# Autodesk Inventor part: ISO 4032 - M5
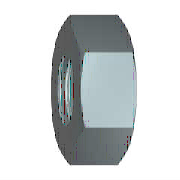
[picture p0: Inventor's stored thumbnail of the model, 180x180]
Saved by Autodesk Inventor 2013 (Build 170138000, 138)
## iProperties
Created: 2012-02
Part Number: ISO 4032 - M5
Material: Edelstahl, 440C
Description: Sechskantmuttern, Typ 1 - Produktklasse A und B
Document SubType Name: Modeling
Standard: ISO 4032
Designer: Dan
Standard Revision: Third edition 1999-08-15
Standards Organization: ISO
Language: de-DE
Size Designation: M5
Categories: <MemberInstance><Categories><Category DisplayName="Verbindungselemente" InternalName="e4da775c-781d-43d5-af7c-5136215cf5a6" Mnemonic="FSTN"><Category DisplayNam
Density: 7.75 g/cm^3
IsCustomPart: 0
Author: Dan
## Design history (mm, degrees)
sketch "Skizze1"
  geometry: L1 (-4.619, 0)-(-2.309, 4); L2 (-2.309, 4)-(2.309, 4); L3 (2.309, 4)-(4.619, 0); L4 (4.619, 0)-(2.309, -4); L5 (2.309, -4)-(-2.309, -4); L6 (-2.309, -4)-(-4.619, 0); 2 further points
  constraints: 12 end point, 1 coincident, 1 horizontal, 11 other
  dimensions: "d0" = 9.2376 distance of L3.end L1.start (= 1.1547 x SW)
extrude "Körper" new body sketch "Skizze1" distance "d1" = 4.7 (= KOH); taper "d2" = 0 deg
sketch "Skizze2"
  geometry: L1 (0, 2.309)-(0, 4.619) reference; L2 (0, 4.619)-(4.7, 4.619) reference; L3 (4.7, 2.309)-(4.7, 4.619) reference; L4 (-0.94, 0)-(5.64, 0) reference; L5 (0.675, 4.619)-(0, 3.45); L6 (4.025, 4.619)-(4.7, 3.45)
  constraints: 4 end point, 4 point on line
  dimensions: "d3" = 30 deg angle of L1 L5 (= ANG1); "d4" = 30 deg angle of L3 L6 (= ANG2); "d5" = 6.9 diameter of L5.end L4 (= SW0); "d6" = 6.9 diameter of L6.end L4 (= SW01)
revolve "Fase1" sketch "Skizze2" stored, may be unused: angle "d7" = 90 deg
sketch "Skizze3"
  geometry: 4 further points
  constraints: 1 coincident, 1 other
hole "Gewinde" sketch "Skizze3" at (0, 0) diameter "d25" = 4.134; stored, may be unused: countersink angle "d29" = 82 deg, drill point angle "d31" = 118 deg; dims "d26" = 6, "d27" = 4, "d28" = 2, "d30" = 8
workaxis "Work Axis1"
workplane "Work Plane1"
body "Solid1"
chamfer "Fase2" distance "d8" = 0.43301 (= -0.5 x GD1 + 0.5 x NND); stored, may be unused: angle "d9" = 30 deg, second distance "d40" = 0.43301 (= -0.5 x GD1 + 0.5 x NND)
chamfer "Fase3" distance "d10" = 0.43301 (= -0.5 x GD1 + 0.5 x NND); stored, may be unused: angle "d11" = 30 deg, second distance "d41" = 0.43301 (= -0.5 x GD1 + 0.5 x NND)
other parameters: "ANG1" = 30 deg [user parameter; used in 1 equation term], "ANG2" = 30 deg [user parameter; used in 1 equation term], "NND" = 5 [user parameter; used in 4 equation terms], "KOH" = 4.7 [user parameter; used in 1 equation term], "SW" = 8 [user parameter; used in 2 equation terms], "SW0" = 6.9 [user parameter; used in 2 equation terms], "SW01" = 6.9 (= SW0) [user parameter; used in 1 equation term], "GD1" = 4.13397 (computed from THREADDIA, PTC, TOA) [user parameter; used in 4 equation terms], "d13" = 0, "d14" = 0, "d39" = 0, "d42" = 0, "GUL" = 0.43301 (= 0.541266 x PTC) [user parameter], "TPU" = 12.5 (computed from PTC) [user parameter], "THREADDIA" = 5 [user parameter; used in 1 equation term], "TOA" = 30 deg [user parameter; used in 1 equation term], "PTC" = 0.8 [user parameter; used in 4 equation terms], "E0" = 9.24 (= 1.155 x SW) [user parameter], "GAL" = 0.43301 (= 0.541266 x PTC) [user parameter]
